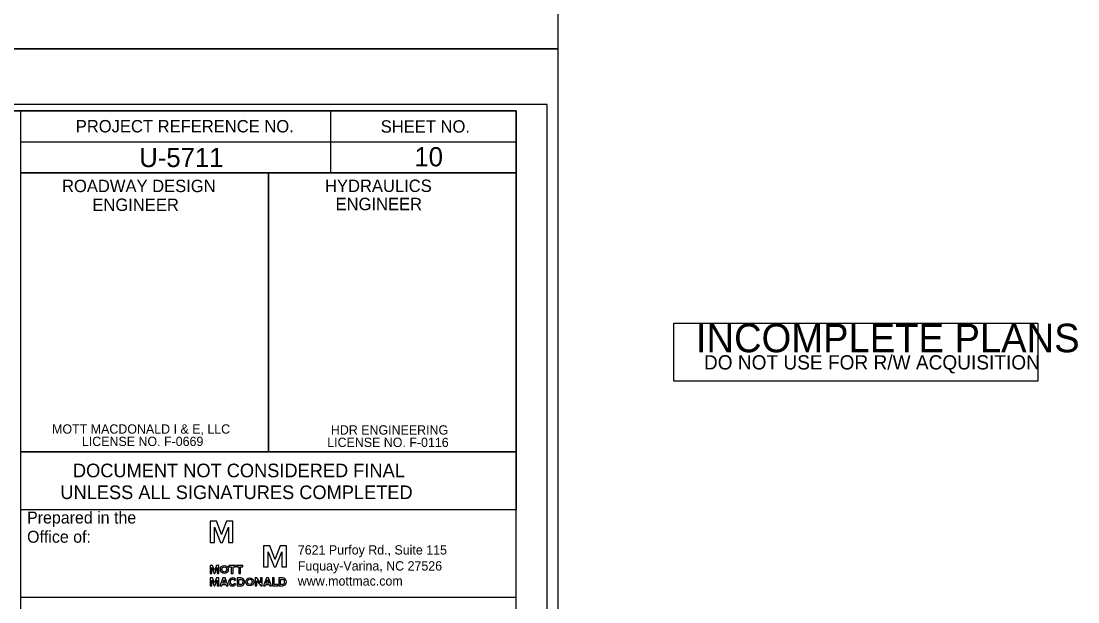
# Model space of a CAD drawing. Extents: x 1754992 to 1757273, y 732111 to 735411.
# Drawn here: x 1756647.8 to 1757074.5, y 732987.6 to 733222 of the extents above; entities that cross this region are included whole.
import ezdxf

# ---------------------------------------------------------------- set-up
doc = ezdxf.new("R2010")
doc.units = 0
for name, color, linetype in [('Old_Level_2', 7, 'Continuous'), ('Old_Level_3', 7, 'Continuous'), ('Old_Level_42', 7, 'Continuous'), ('Old_Level_45', 7, 'Continuous'), ('Sheet Cutting Line CELL', 7, 'Continuous'), ('Sheet Data Field CELL', 7, 'Continuous'), ('Sheet Plot Border Inside CELL', 7, 'Continuous'), ('Sheet Plot Border Outside CELL', 7, 'Continuous'), ('Sheet Profile CELL', 7, 'Continuous'), ('Sheet Profile Grid Major CELL', 7, 'Continuous'), ('Sheet Profile Grid Minor CELL', 7, 'Continuous'), ('Sheet Sticker Exception Certification CELL', 7, 'Continuous'), ('Sheet Sticker Incomplete CELL', 7, 'Continuous')]:
    doc.layers.add(name, color=color, linetype=linetype)

msp = doc.modelspace()

# ---------------------------------------------------------------- linework, layer by layer
at = {"layer": 'Old_Level_2'}
for p, q in [((1756726.6, 733020.13), (1756724.08, 733020.13)), ((1756724.08, 733020.13), (1756724.08, 733011.63)), ((1756728.65, 733014.88), (1756726.6, 733020.13)), ((1756730.76, 733020.13), (1756728.71, 733014.88)), ((1756733.28, 733020.13), (1756730.76, 733020.13)), ((1756733.28, 733011.63), (1756733.28, 733020.13)), ((1756725.87, 733011.63), (1756725.87, 733017.74)), ((1756725.87, 733017.74), (1756725.9, 733017.74)), ((1756725.9, 733017.74), (1756728.29, 733011.63)), ((1756728.65, 733014.8), (1756728.65, 733014.88)), ((1756728.71, 733014.8), (1756728.65, 733014.8)), ((1756728.71, 733014.88), (1756728.71, 733014.8)), ((1756729.07, 733011.63), (1756731.46, 733017.77)), ((1756731.46, 733017.77), (1756731.49, 733017.77)), ((1756731.49, 733017.77), (1756731.49, 733011.63)), ((1756724.08, 733011.63), (1756725.87, 733011.63)), ((1756728.29, 733011.63), (1756729.07, 733011.63)), ((1756731.49, 733011.63), (1756733.28, 733011.63)), ((1756748.21, 733010.23), (1756745.69, 733010.23)), ((1756745.69, 733010.23), (1756745.69, 733001.73)), ((1756750.27, 733004.98), (1756748.21, 733010.23)), ((1756752.37, 733010.23), (1756750.32, 733004.98)), ((1756754.9, 733010.23), (1756752.37, 733010.23)), ((1756754.9, 733001.73), (1756754.9, 733010.23)), ((1756747.49, 733001.73), (1756747.49, 733007.84)), ((1756747.49, 733007.84), (1756747.51, 733007.84)), ((1756747.51, 733007.84), (1756749.9, 733001.73)), ((1756750.68, 733001.73), (1756753.08, 733007.86)), ((1756753.08, 733007.86), (1756753.1, 733007.86)), ((1756753.1, 733007.86), (1756753.1, 733001.73)), ((1756725.04, 733002.33), (1756724.08, 733002.33)), ((1756724.08, 733002.33), (1756724.08, 732999.08)), ((1756725.85, 733000.3), (1756725.04, 733002.33)), ((1756726.65, 733002.33), (1756725.85, 733000.3)), ((1756727.61, 733002.33), (1756726.65, 733002.33)), ((1756727.61, 732999.08), (1756727.61, 733002.33)), ((1756727.61, 732999.08), (1756727.61, 733002.33)), ((1756745.69, 733001.73), (1756747.49, 733001.73)), ((1756749.9, 733001.73), (1756750.68, 733001.73)), ((1756750.27, 733004.9), (1756750.27, 733004.98)), ((1756750.32, 733004.9), (1756750.27, 733004.9)), ((1756750.32, 733004.98), (1756750.32, 733004.9)), ((1756753.1, 733001.73), (1756754.9, 733001.73)), ((1756724.08, 732999.08), (1756724.75, 732999.08)), ((1756724.75, 732999.08), (1756724.75, 733001.42)), ((1756724.75, 733001.42), (1756724.78, 733001.42)), ((1756724.75, 733001.42), (1756724.78, 733001.42)), ((1756724.78, 733001.42), (1756725.69, 732999.08)), ((1756725.69, 732999.08), (1756726, 732999.08)), ((1756726, 732999.08), (1756726.91, 733001.42)), ((1756726.91, 733001.42), (1756726.94, 733001.42)), ((1756726.91, 733001.42), (1756726.94, 733001.42)), ((1756726.91, 733001.42), (1756726.94, 733001.42)), ((1756726.94, 733001.42), (1756726.94, 732999.08)), ((1756726.94, 732999.08), (1756727.61, 732999.08)), ((1756725.04, 732997.28), (1756724.08, 732997.28)), ((1756724.08, 732997.28), (1756724.08, 732994.03)), ((1756724.08, 732994.03), (1756724.75, 732994.03)), ((1756724.75, 732994.03), (1756724.75, 732996.37)), ((1756724.75, 732996.37), (1756724.78, 732996.37)), ((1756724.78, 732996.37), (1756725.69, 732994.03)), ((1756725.85, 732995.25), (1756725.04, 732997.28)), ((1756725.69, 732994.03), (1756726, 732994.03)), ((1756726.65, 732997.28), (1756725.85, 732995.25)), ((1756726, 732994.03), (1756726.91, 732996.37)), ((1756727.61, 732997.28), (1756726.65, 732997.28)), ((1756726.91, 732996.37), (1756726.94, 732996.37)), ((1756726.94, 732996.37), (1756726.94, 732994.03)), ((1756726.94, 732994.03), (1756727.61, 732994.03)), ((1756727.61, 732994.03), (1756727.61, 732997.28)), ((1756734.44, 732994.7), (1756733.88, 732994.98)), ((1756734.44, 732994.7), (1756733.88, 732994.98)), ((1756733.96, 732996.22), (1756734.52, 732996.49)), ((1756733.96, 732996.22), (1756734.52, 732996.49)), ((1756736.45, 732997.28), (1756734.97, 732997.28)), ((1756734.97, 732997.28), (1756734.97, 732995.6)), ((1756734.97, 732995.6), (1756734.97, 732994.03)), ((1756734.97, 732994.03), (1756736.45, 732994.03)), ((1756735.65, 732994.66), (1756735.65, 732996.68)), ((1756735.65, 732996.68), (1756736.45, 732996.68)), ((1756736.45, 732994.66), (1756735.65, 732994.66)), ((1756751.79, 732997.28), (1756751.79, 732997.28)), ((1756753.27, 732997.28), (1756751.79, 732997.28)), ((1756751.79, 732997.28), (1756751.79, 732995.6)), ((1756751.79, 732995.6), (1756751.79, 732994.03)), ((1756751.79, 732994.03), (1756753.27, 732994.03)), ((1756752.46, 732994.66), (1756752.46, 732996.68)), ((1756752.46, 732996.68), (1756753.27, 732996.68)), ((1756753.27, 732994.66), (1756752.46, 732994.66)), ((1756753.27, 732996.66), (1756753.27, 732996.66))]:
    msp.add_line(p, q, dxfattribs=at)
for points in [[(1756731.69, 733001.73), (1756732.63, 733001.73), (1756732.63, 732999.08), (1756733.33, 732999.08), (1756733.33, 733001.73), (1756734.27, 733001.73), (1756734.27, 733002.33), (1756731.69, 733002.33), (1756731.69, 733001.73)], [(1756734.68, 733001.73), (1756735.62, 733001.73), (1756735.62, 732999.08), (1756736.32, 732999.08), (1756736.32, 733001.73), (1756737.26, 733001.73), (1756737.26, 733002.33), (1756734.68, 733002.33), (1756734.68, 733001.73)], [(1756728, 732994.03), (1756728.78, 732994.03), (1756728.99, 732994.58), (1756730.4, 732994.58), (1756730.6, 732994.03), (1756731.36, 732994.03), (1756730.11, 732997.28), (1756729.25, 732997.28), (1756728, 732994.03)], [(1756729.17, 732995.18), (1756729.69, 732996.58), (1756730.21, 732995.18), (1756729.17, 732995.18)], [(1756742.92, 732996.14), (1756742.95, 732996.14), (1756744.51, 732994.03), (1756745.16, 732994.03), (1756745.16, 732997.28), (1756744.48, 732997.28), (1756744.48, 732995.23), (1756742.95, 732997.28), (1756742.27, 732997.28), (1756742.27, 732994.03), (1756742.92, 732994.03), (1756742.92, 732996.14)], [(1756745.58, 732994.03), (1756746.35, 732994.03), (1756746.56, 732994.58), (1756747.97, 732994.58), (1756748.17, 732994.03), (1756748.93, 732994.03), (1756747.68, 732997.28), (1756746.82, 732997.28), (1756745.58, 732994.03)], [(1756746.75, 732995.18), (1756747.27, 732996.58), (1756747.79, 732995.18), (1756746.75, 732995.18)], [(1756751.4, 732994.03), (1756751.4, 732994.61), (1756749.99, 732994.61), (1756749.99, 732997.28), (1756749.32, 732997.28), (1756749.32, 732994.03), (1756751.4, 732994.03)], [(1756751.4, 732994.03), (1756751.4, 732994.61), (1756749.99, 732994.61), (1756749.99, 732997.28), (1756749.32, 732997.28), (1756749.32, 732994.03), (1756751.4, 732994.04), (1756751.4, 732994.61)]]:
    msp.add_lwpolyline(points, dxfattribs=at)
msp.add_arc((1756753.27, 732995.66), 1.62, 270, 90, dxfattribs=at)
for centre, major_axis, ratio in [((1756729.82, 733000.7), (0, 1.62), 0.993118), ((1756729.82, 733000.7), (0, 1.06), 0.916103), ((1756740.09, 732995.66), (0, 1.62), 0.993118), ((1756740.09, 732995.66), (0, 1.06), 0.916103)]:
    msp.add_ellipse(centre, major_axis=major_axis, ratio=ratio, dxfattribs=at)
for centre, major_axis, ratio, start_param, end_param in [((1756733.14, 732995.66), (0, 1.62), 0.993118, 5.246647, 10.366427), ((1756733.14, 732995.66), (0, 1.62), 0.993118, 5.246647, 10.366427), ((1756733.14, 732995.66), (0, 1.06), 0.916103, 5.276876, 9.424778), ((1756733.14, 732995.66), (0, 1.06), 0.916103, 5.276876, 10.296021), ((1756733.14, 732995.66), (0, 1.06), 0.916103, 3.141593, 4.012835), ((1756736.45, 732995.66), (0, -1.62), 0.930276, 0, 3.141593), ((1756736.45, 732995.67), (0, -1.01), 0.900832, 0, 3.141593), ((1756753.27, 732995.67), (0, -1.01), 0.900832, 0, 3.141593)]:
    msp.add_ellipse(centre, major_axis=major_axis, ratio=ratio, start_param=start_param, end_param=end_param, dxfattribs=at)
at = {"layer": 'Old_Level_42'}
msp.add_lwpolyline([(1756847.67, 732989.43), (1756647.62, 732989.43), (1756647.62, 733024.73)], dxfattribs=at)
at = {"layer": 'Sheet Cutting Line CELL'}
for p, q in [((1756864.67, 733210.78), (1755180.67, 733210.78)), ((1755180.67, 733210.78), (1756864.67, 733210.78))]:
    msp.add_line(p, q, dxfattribs=at)
at = {"layer": 'Sheet Plot Border Inside CELL'}
msp.add_lwpolyline([(1755193.67, 732133.23), (1756860.17, 732133.23), (1756860.17, 733188.33), (1755193.67, 733188.33)], close=True, dxfattribs=at)
at = {"layer": 'Sheet Plot Border Outside CELL'}
for points in [[(1755180.67, 733210.78), (1756864.67, 733210.78), (1756864.67, 734310.78), (1755180.67, 734310.78)], [(1755180.67, 732110.78), (1756864.67, 732110.78), (1756864.67, 733210.78), (1755180.67, 733210.78)]]:
    msp.add_lwpolyline(points, close=True, dxfattribs=at)
at = {"layer": 'Sheet Profile CELL'}
for p, q in [((1756772.67, 733185.73), (1756772.67, 733160.73)), ((1756647.62, 733173.23), (1756847.67, 733173.23)), ((1756747.67, 733160.73), (1756747.67, 733048.28))]:
    msp.add_line(p, q, dxfattribs=at)
for points in [[(1756847.67, 733185.78), (1755347.67, 733185.78), (1755347.67, 732135.78), (1756847.67, 732135.78)], [(1756647.62, 733185.78), (1756847.67, 733185.78), (1756847.67, 733160.73), (1756647.62, 733160.73)], [(1756647.62, 733160.73), (1756747.67, 733160.73), (1756747.67, 733048.23), (1756647.62, 733048.23)], [(1756747.67, 733160.73), (1756847.67, 733160.73), (1756847.67, 733048.23), (1756747.67, 733048.23)]]:
    msp.add_lwpolyline(points, close=True, dxfattribs=at)
at = {"layer": 'Sheet Profile Grid Major CELL'}
for points in [[(1756097.67, 732685.78), (1756147.67, 732685.78), (1756147.67, 733185.78), (1756197.67, 733185.78), (1756197.67, 732685.78), (1756247.67, 732685.78), (1756247.67, 733185.78), (1756297.67, 733185.78), (1756297.67, 732685.78), (1756347.67, 732685.78), (1756347.67, 733185.78), (1756397.67, 733185.78), (1756397.67, 732685.78), (1756447.67, 732685.78), (1756447.67, 733185.78), (1756497.67, 733185.78), (1756497.67, 732685.78), (1756547.67, 732685.78), (1756547.67, 733185.78), (1756597.67, 733185.78), (1756597.67, 732685.78), (1756647.67, 732685.78), (1756647.67, 733185.78), (1756673.97, 733185.78)], [(1756797.67, 732952.66), (1756797.67, 732685.78), (1756847.67, 732685.78), (1756847.67, 733035.78)]]:
    msp.add_lwpolyline(points, dxfattribs=at)
at = {"layer": 'Sheet Profile Grid Minor CELL'}
msp.add_lwpolyline([(1756642.67, 733185.78), (1756652.67, 733185.78)], dxfattribs=at)
at = {"layer": 'Sheet Sticker Exception Certification CELL'}
for p, q in [((1756647.62, 733048.23), (1756847.66, 733048.23)), ((1756647.62, 733048.23), (1756847.66, 733048.23)), ((1756847.66, 733048.22), (1756847.66, 733024.72)), ((1756847.66, 733048.22), (1756847.66, 733024.72)), ((1756847.66, 733024.73), (1756647.62, 733024.73)), ((1756847.66, 733024.73), (1756647.62, 733024.73))]:
    msp.add_line(p, q, dxfattribs=at)
at = {"layer": 'Sheet Sticker Incomplete CELL'}
msp.add_lwpolyline([(1756911.29, 733076.65), (1756911.29, 733100.15), (1757058.29, 733100.15), (1757058.29, 733076.65)], close=True, dxfattribs=at)

# ---------------------------------------------------------------- texts
at = {"layer": 'Old_Level_2'}
for s, height, p in [('Prepared in the ', 4.8186, (1756650.17, 733019.23)), ('Office of:', 4.819, (1756650.17, 733011.48))]:
    msp.add_text(s, height=height, dxfattribs=at).set_placement(p)
for s, p in [('7621 Purfoy Rd., Suite 115', (1756759.5, 733006.71)), ('Fuquay-Varina, NC 27526', (1756759.5, 733000.26)), ('www.mottmac.com', (1756759.5, 732994.17))]:
    msp.add_text(s, height=3.75, rotation=360, dxfattribs=at).set_placement(p)
at = {"layer": 'Old_Level_3'}
for s, p in [('HDR ENGINEERING', (1756772.84, 733055.13)), (' LICENSE NO. F-0116', (1756769.97, 733050.13))]:
    msp.add_text(s, height=3.75, rotation=360, dxfattribs=at).set_placement(p)
at = {"layer": 'Old_Level_45'}
for s, p in [('MOTT MACDONALD I & E, LLC', (1756660.28, 733055.51)), (' LICENSE NO. F-0669', (1756670.91, 733050.51))]:
    msp.add_text(s, height=3.75, rotation=360, dxfattribs=at).set_placement(p)
at = {"layer": 'Sheet Data Field CELL'}
for s, p in [('U-5711', (1756695.48, 733163.1)), ('10', (1756806.58, 733163.4))]:
    msp.add_text(s, height=7.75, dxfattribs=at).set_placement(p)
at = {"layer": 'Sheet Profile CELL'}
for s, height, p in [('PROJECT REFERENCE NO.', 5.0001, (1756669.83, 733177.1)), ('SHEET NO.', 5, (1756792.98, 733177)), ('ROADWAY DESIGN', 5.0001, (1756664.28, 733153)), ('HYDRAULICS', 5, (1756770.48, 733153.05)), ('ENGINEER', 5, (1756676.53, 733145.4)), ('ENGINEER', 5, (1756774.73, 733145.7))]:
    msp.add_text(s, height=height, dxfattribs=at).set_placement(p)
at = {"layer": 'Sheet Sticker Exception Certification CELL'}
for s, p in [('DOCUMENT NOT CONSIDERED FINAL', (1756668.69, 733037.89)), ('DOCUMENT NOT CONSIDERED FINAL', (1756668.69, 733037.89)), ('UNLESS ALL SIGNATURES COMPLETED', (1756663.62, 733029.09)), ('UNLESS ALL SIGNATURES COMPLETED', (1756663.62, 733029.09))]:
    msp.add_text(s, height=5.5, dxfattribs=at).set_placement(p)
at = {"layer": 'Sheet Sticker Incomplete CELL'}
for s, height, p in [('INCOMPLETE PLANS', 11.52, (1756920.24, 733088.35)), ('DO NOT USE FOR R/W ACQUISITION', 5.76, (1756923.49, 733081.4))]:
    msp.add_text(s, height=height, dxfattribs=at).set_placement(p)

doc.saveas('drawing.dxf')
